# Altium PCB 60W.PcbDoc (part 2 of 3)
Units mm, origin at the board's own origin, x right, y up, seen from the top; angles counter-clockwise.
Board outline 118.9 x 83.5 mm, 3 copper layers (Top Layer, Mid-Layer 2, Bottom Layer); 99 components, 61 nets, 240 pads, 0 vias.
Unrouted connection lines stored in the file: 1.
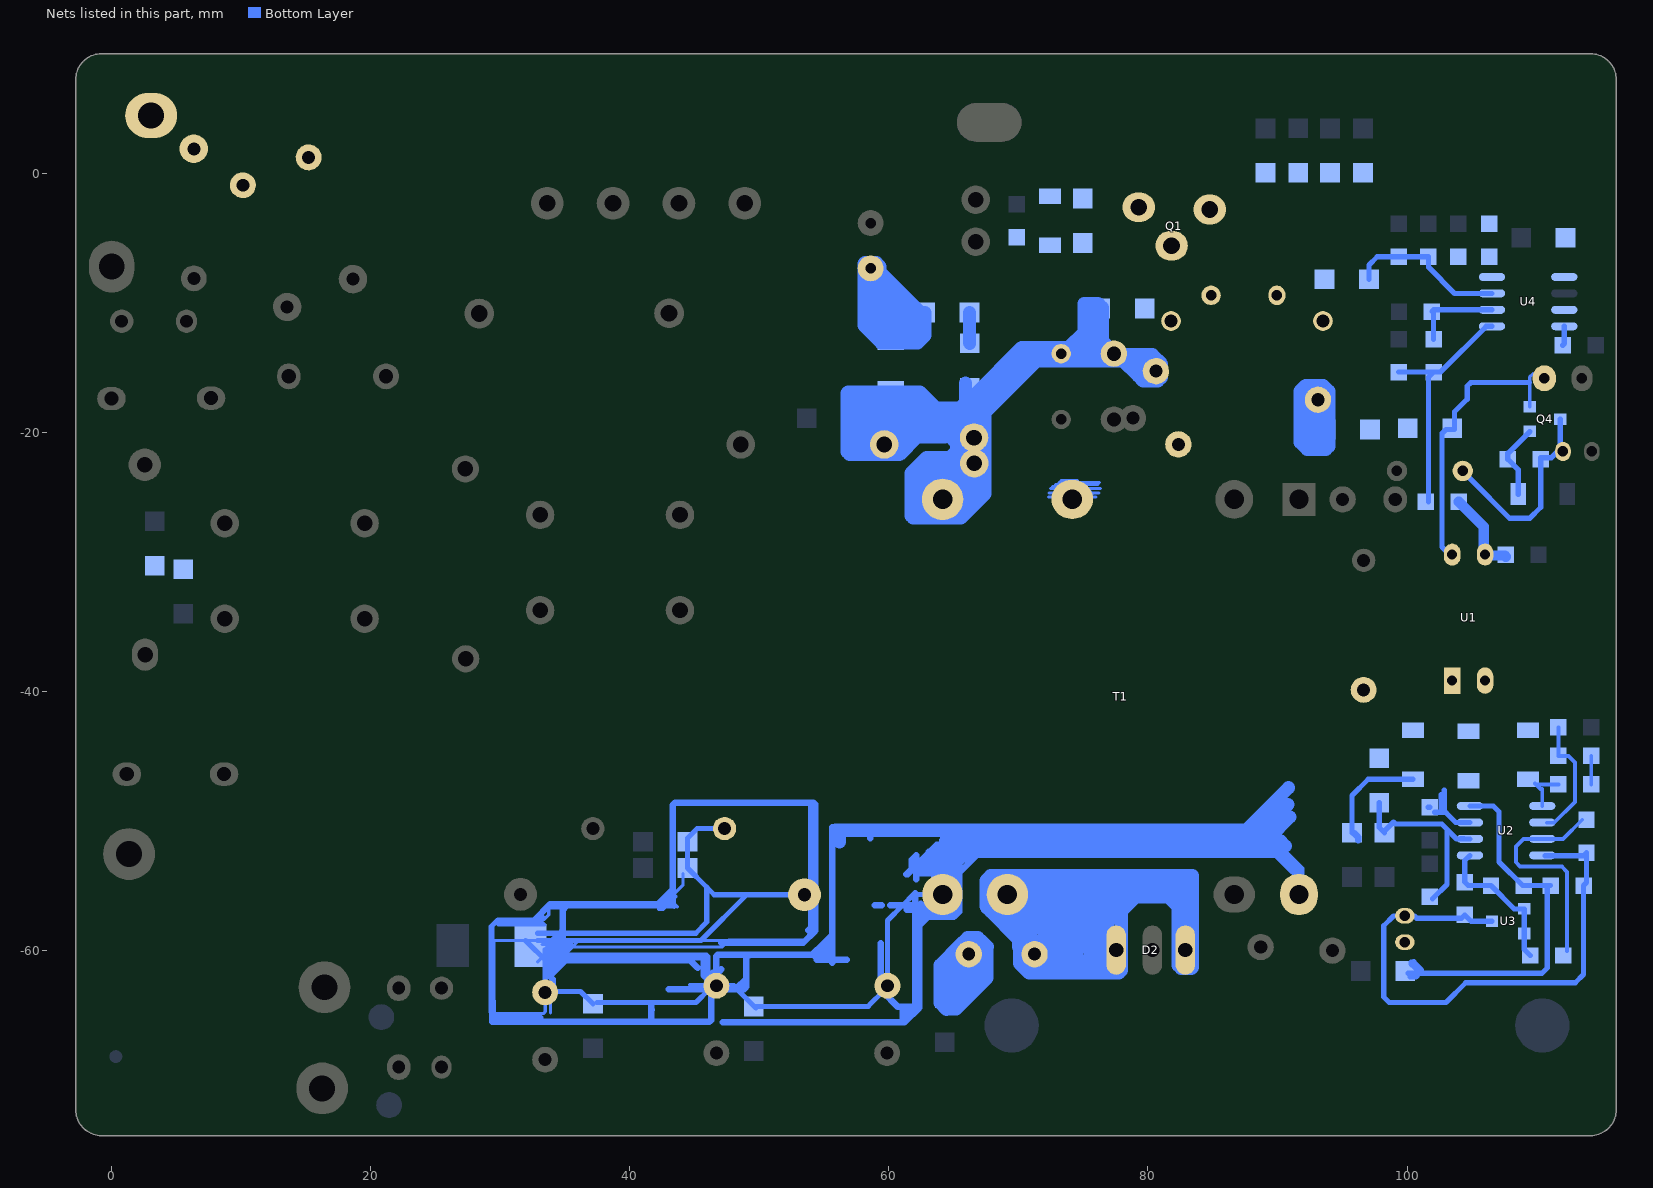
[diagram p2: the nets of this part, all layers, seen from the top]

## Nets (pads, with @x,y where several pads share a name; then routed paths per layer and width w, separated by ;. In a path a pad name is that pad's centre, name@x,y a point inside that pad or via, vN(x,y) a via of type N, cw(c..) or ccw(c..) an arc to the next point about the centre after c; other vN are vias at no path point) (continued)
NewNet1: C1.1 CB1.1 D6.1 L4.1 pad.0@66.605,-22.358 R3.1 R4.1 R11.2 R13.1 R15.2 T1.6 | length 251.5
  Bottom Layer w0.254: T1.6@64.323,-24.728 64.323,-24.509 T1.6@64.323,-23.752
  Bottom Layer w1: 57.284,-17.303 57.284,-18.878 57.284,-19.564 57.487,-19.767 57.919,-19.767 57.792,-19.64 57.792,-18.878 57.792,-16.973 57.919,-16.846 ; 57.715,-20.707 59.658,-20.707 L4.1@60.459,-20.707 ; 58.122,-18.269 58.427,-18.269 ; 58.808,-17.735 60.154,-17.735 61.144,-17.735 61.195,-17.786 ; D6.1@59.443,-17.786 60.154,-17.786 61.195,-17.786 ; 59.722,-19.107 59.417,-19.107 58.579,-18.269 58.427,-18.269 ; 61.754,-18.345 61.474,-18.065 ; 62.516,-19.056 60.51,-19.056 59.519,-18.065 60.154,-18.065 61.474,-18.065 ; T1.6@62.669,-24.771 62.669,-25.142 62.669,-25.787 63.091,-26.21 T1.6@63.177,-26.295 ; 62.719,-20.046 62.49,-20.046 62.269,-20.268 ; T1.6@62.948,-25.152 63.431,-25.635 63.431,-25.142 T1.6@63.431,-24.898 ; T1.6@63.558,-24.644 63.609,-24.592 T1.6@63.939,-24.263 ; T1.6@63.685,-24.644 63.673,-24.656 T1.6@63.431,-24.898 ; 63.812,-18.091 65.462,-18.091 ; T1.6@63.909,-25.142 64.034,-25.017 T1.6@64.182,-24.868 ; T1.6@64.182,-24.654 T1.6@64.182,-24.868 ; T1.6@64.193,-24.858 T1.6@64.182,-24.868 ; 64.193,-19.818 64.218,-19.818 ; 64.32,-20.326 62.211,-20.326 ; T1.6@64.447,-24.604 T1.6@64.432,-24.618 ; T1.6@64.548,-26.117 T1.6@64.726,-26.295 ; 64.828,-22.18 64.548,-21.901 ; 64.979,-19.996 64.396,-19.996 ; 64.98,-20.402 65.005,-20.378 ; 65.361,-20.402 65.488,-20.529 ; CB1.1@65.818,-20.351 65.818,-20.378 65.818,-22.358 65.818,-24.746 65.59,-24.974 T1.6@65.209,-24.974 ; R13.1@65.92,-16.161 65.92,-16.528 65.92,-17.634 65.462,-18.091 ; 69.501,-14.23 66.726,-17.005 65.64,-18.091 ; 75.369,-11.766 75.369,-11.919 ; 75.623,-13.697 75.572,-13.697 75.369,-13.493 75.369,-11.919 ; R15.2@75.623,-10.903 75.731,-11.011 76.029,-11.309 76.029,-12.935 76.156,-12.808 76.156,-10.42 R15.2@76.156,-10.014 ; R4.1@80.703,-15.195 80.687,-15.18 79.966,-14.459 79.077,-14.459 ; 56.776,-20.504 57.614,-21.342 59.658,-21.342 60.68,-21.342 ; 56.776,-20.504 56.776,-20.123 ; 56.776,-20.504 56.776,-21.494 56.979,-21.697 59.658,-21.697 L4.1@60.325,-21.697 ; 56.776,-20.123 56.979,-20.326 59.658,-20.326 61.696,-20.326 ; 56.776,-20.123 56.776,-18.878 56.776,-16.922 56.852,-16.846 57.919,-16.846 ; 57.919,-16.846 58.579,-16.846 ; 58.427,-18.827 58.427,-18.269 ; 58.427,-18.827 58.427,-19.691 59.004,-20.268 59.658,-20.268 61.754,-20.268 ; 58.427,-18.827 58.96,-19.361 59.658,-19.361 63.761,-19.361 ; 58.427,-18.269 58.427,-16.999 58.579,-16.846 ; 58.579,-16.846 60.154,-16.846 62.415,-16.846 64.624,-19.056 ; L4.1@60.325,-21.697 60.385,-21.637 60.68,-21.342 ; L4.1@60.325,-21.697 60.839,-21.697 62.211,-20.326 ; 60.68,-21.342 61.696,-20.326 ; 61.195,-17.786 61.474,-18.065 ; 61.195,-17.786 62.186,-17.786 63.05,-18.65 ; 61.474,-18.065 62.008,-18.065 62.592,-18.65 63.05,-18.65 ; 61.696,-20.326 62.211,-20.326 ; 61.696,-20.326 61.754,-20.268 ; 61.754,-20.268 62.269,-20.268 ; 62.211,-20.326 62.269,-20.268 ; 62.269,-20.268 64.668,-20.268 ; 62.44,-22.383 62.923,-21.901 64.548,-21.901 ; 62.44,-22.383 61.729,-23.095 61.729,-26.422 61.881,-26.574 64.159,-26.574 65.59,-26.574 65.59,-26.574 66.834,-25.33 ; 62.44,-22.383 62.44,-25.142 62.44,-25.863 62.872,-26.295 T1.6@63.177,-26.295 ; 63.05,-18.65 63.761,-19.361 ; T1.6@63.177,-26.295 64.244,-25.227 T1.6@64.432,-25.04 ; T1.6@63.177,-26.295 64.159,-26.295 T1.6@64.726,-26.295 ; T1.6@63.431,-24.898 63.431,-22.51 63.989,-21.952 63.989,-24.176 64.323,-24.509 T1.6@64.432,-24.618 ; 63.761,-19.361 64.218,-19.818 ; 64.218,-19.818 64.548,-19.818 64.967,-19.399 ; 64.218,-19.818 64.396,-19.996 ; 64.396,-19.996 64.668,-20.268 ; T1.6@64.432,-25.04 T1.6@64.432,-24.618 ; T1.6@64.432,-25.04 64.432,-25.142 64.432,-25.294 64.548,-25.177 64.548,-25.142 T1.6@64.548,-24.974 ; T1.6@64.432,-25.04 64.497,-24.974 T1.6@64.548,-24.974 ; T1.6@64.548,-24.974 T1.6@65.209,-24.974 ; T1.6@64.548,-24.974 64.548,-21.901 ; 64.548,-21.901 64.726,-21.901 ; 64.624,-19.056 65.59,-18.091 ; 64.624,-19.056 64.193,-19.488 64.193,-19.539 64.65,-19.081 ; 64.624,-19.056 64.65,-19.081 ; 64.65,-19.081 65.64,-18.091 ; 64.65,-19.081 64.967,-19.399 ; 64.668,-20.268 65.005,-20.605 ; T1.6@64.726,-26.295 65.019,-26.002 65.209,-25.812 65.209,-25.142 T1.6@65.209,-24.974 ; T1.6@64.726,-26.295 65.132,-26.295 65.222,-26.205 66.317,-25.11 66.317,-22.358 66.317,-20.378 66.317,-19.065 ; 64.726,-21.901 65.209,-21.418 ; 64.726,-21.901 65.158,-21.901 65.209,-21.85 ; 64.967,-19.399 67.044,-17.322 70.39,-13.976 71.914,-13.976 ; 64.967,-19.399 65.005,-19.436 65.005,-20.378 ; 65.005,-20.605 65.005,-20.378 ; 65.005,-20.605 65.209,-20.809 65.209,-21.418 ; 65.005,-20.378 65.792,-19.59 66.317,-19.065 ; T1.6@65.209,-24.974 65.209,-22.358 65.209,-21.85 ; 65.209,-21.85 65.209,-21.418 ; 65.462,-18.091 65.59,-18.091 ; 65.59,-18.091 66.701,-16.98 70.263,-13.417 73.311,-13.417 C1.1@73.87,-13.417 ; 65.59,-18.091 65.64,-18.091 ; 66.317,-19.065 70.924,-14.459 71.406,-14.459 ; 66.834,-25.33 66.834,-22.358 66.834,-20.378 66.834,-19.056 67.418,-18.472 ; 66.834,-25.33 67.418,-24.746 67.418,-22.358 67.418,-20.378 67.418,-18.472 ; 67.418,-18.472 71.432,-14.459 ; 67.418,-18.472 67.418,-18.447 71.406,-14.459 ; 71.406,-14.459 71.432,-14.459 ; 71.432,-14.459 73.311,-14.459 77.375,-14.459 R3.1@78.061,-14.459 ; 71.432,-14.459 71.914,-13.976 ; 71.914,-13.976 73.311,-13.976 R3.1@76.486,-13.976 ; C1.1@73.87,-13.417 75.064,-12.223 ; C1.1@73.87,-13.417 74.556,-13.417 75.064,-12.909 75.064,-12.223 ; 75.064,-12.223 75.064,-10.42 75.064,-10.014 R15.2@76.156,-10.014 ; 75.064,-12.223 75.369,-11.919 ; R15.2@76.156,-10.014 76.442,-10.299 76.486,-10.344 76.486,-10.42 76.486,-12.884 ; R3.1@76.486,-13.976 76.486,-13.9 76.486,-12.884 ; R3.1@76.486,-13.976 77.375,-13.976 R3.1@77.578,-13.976 ; 76.486,-12.884 77.439,-13.836 R3.1@77.578,-13.976 ; R3.1@77.578,-13.976 80.347,-13.976 81.058,-14.687 81.058,-15.251 81.058,-15.729 80.779,-16.008 80.616,-16.008 79.61,-16.008 79.229,-15.627 ; R3.1@78.061,-14.459 79.077,-14.459 ; R3.1@78.061,-14.459 79.229,-15.627 ; 79.077,-14.459 79.229,-14.611 79.229,-15.251 79.229,-15.627
NewNet2: 
NewNet3: R4.2 R21.2 | length 29.2
  Bottom Layer w0.6: 92.75,-20.766 92.75,-19.75 92.75,-19.475 92.85,-19.375 ; 93.35,-21.291 93.35,-19.75 93.35,-19.185 R21.2@93.377,-19.158
  Bottom Layer w1: 92.92,-20.936 92.75,-20.766 92.727,-20.743 92.361,-20.377 92.361,-19.158 ; R4.2@92.996,-17.202 R4.2@92.996,-16.948 ; 93.479,-18.904 93.479,-18.548 ; R4.2@93.479,-17.227 93.479,-17.456 R4.2@93.479,-18.218 ; 91.752,-18.752 92.158,-19.158 92.361,-19.158 ; 91.751,-18.752 91.751,-20.758 92.285,-21.291 93.35,-21.291 93.733,-21.291 93.961,-21.063 93.961,-19.75 93.961,-18.573 ; 91.752,-18.752 91.752,-18.167 ; 91.752,-18.167 92.082,-18.497 92.133,-18.548 92.361,-18.548 ; 91.752,-18.167 91.752,-17.456 91.752,-17.075 ; 91.752,-17.075 91.752,-16.77 92.094,-16.427 92.183,-16.338 93.123,-16.338 93.504,-16.338 93.872,-16.707 93.961,-16.796 93.961,-17.456 93.961,-18.167 ; 91.752,-17.075 92.628,-17.951 92.895,-18.218 93.123,-18.218 R4.2@93.479,-18.218 ; 92.361,-19.158 93.377,-19.158 93.961,-18.573 ; 92.361,-19.158 92.361,-18.548 ; 92.361,-18.548 93.123,-18.548 93.479,-18.548 ; 93.479,-18.548 93.72,-18.548 93.911,-18.548 93.961,-18.497 ; 93.479,-18.548 R4.2@93.479,-18.218 ; R4.2@93.479,-18.218 93.911,-18.218 93.961,-18.167 ; 93.961,-18.573 93.961,-18.497 ; 93.961,-18.497 93.961,-18.167
NewNet4: R6.1 R7.2
NewNet5: C4.1 R2.2 | length 29.9
  Bottom Layer w1: 64.447,-64.497 65.183,-64.497 65.189,-64.49 67.596,-62.084 67.596,-60.25 67.596,-59.671 ; R2.2@66.885,-60.509 67.012,-60.636 67.012,-62.262
  Bottom Layer w1.016: 64.447,-64.497 63.964,-64.014 63.964,-63.621 63.964,-62.668 ; C4.1@64.523,-63.1 65.564,-62.058 ; 65.005,-60.229 63.964,-61.271 ; C4.1@65.031,-63.15 64.65,-63.531 65.234,-63.531 ; 65.564,-62.871 65.996,-62.439 65.996,-62.414 65.602,-62.02 ; 66.352,-62.045 66.352,-61.271 ; R2.2@66.352,-59.696 66.352,-60.25 R2.2@66.352,-60.28 ; R2.2@66.936,-60.28 66.631,-59.975 66.631,-60.001 R2.2@66.352,-60.28 ; 67.596,-59.671 67.175,-59.249 66.885,-58.959 66.174,-58.959 66.098,-58.959 65.491,-59.566 63.964,-61.093 63.964,-61.271 ; 63.964,-62.668 63.964,-61.271 ; 63.964,-62.668 66.278,-60.354 R2.2@66.352,-60.28 ; 65.564,-62.058 65.602,-62.02 ; 65.564,-62.058 65.564,-61.982 65.602,-62.02 ; 65.602,-62.02 66.352,-61.271 ; 66.352,-61.271 R2.2@66.352,-60.28
NewNet6: R12.1 R13.2 | length 2.4
  Bottom Layer w1: R12.1@66.237,-10.725 66.237,-13.087 R13.2@66.25,-13.1
NewNet7: D6.2 E4.1 R12.2 | length 40.3
  Bottom Layer w1: E4.1@58.63,-7.42 58.63,-11.995 59.227,-12.592 D6.2@60.154,-12.592 ; 59.239,-8.414 59.239,-11.538 59.798,-12.097 60.154,-12.097 62.364,-12.097 62.516,-11.944 R12.2@62.516,-11.258 ; 59.925,-8.871 59.925,-10.928 60.382,-11.385 62.008,-11.385 ; 60.23,-10.319 60.687,-10.776 61.348,-10.776 ; 60.382,-9.43 60.382,-9.811 61.348,-10.776 ; 61.906,-10.776 61.348,-10.776 ; 58.096,-11.741 59.417,-13.062 60.154,-13.062 62.237,-13.062 62.809,-12.49 R12.2@62.809,-10.725 62.465,-10.725 59.341,-7.601 59.341,-7.319 59.341,-7.169 59.048,-6.876 59.036,-6.864 58.604,-6.864 58.173,-6.864 58.161,-6.876 58.096,-6.94 58.096,-7.319 58.096,-11.741
NewNet8: D2.1 D2.3 R2.1 T1.8 | length 206.1
  Bottom Layer w0.3: 70.949,-59.125 71.254,-59.125 72.562,-59.125 73.223,-59.125 73.825,-59.125 ; 70.949,-58.9 72.337,-58.9 72.6,-58.9
  Bottom Layer w1.016: T1.8@68.511,-54.997 T1.8@68.882,-54.997 ; T1.8@68.909,-55.642 T1.8@69.159,-55.642 71.381,-55.642 ; T1.8@69.019,-55.403 69.159,-55.403 72.422,-55.403 ; T1.8@69.12,-55.911 69.159,-55.911 71.111,-55.911 ; 70.543,-61.195 71.051,-61.703 71.254,-61.703 74.454,-61.703 ; 70.822,-61.703 70.312,-61.192 70.085,-60.966 70.085,-60.25 70.085,-59.747 ; R2.1@71.432,-59.696 73.133,-59.696 ; D2.3@76.969,-59.95 76.715,-59.696 ; D2.3@77.578,-61.296 D2.3@77.375,-61.093 ; 82.608,-55.124 82.862,-54.87 82.862,-55.657 ; 82.862,-57.08 82.862,-55.657 ; D2.1@83.09,-58.172 82.557,-57.639 82.557,-56.826 82.328,-56.597 ; T1.8@68.882,-54.997 69.095,-55.21 69.159,-55.21 72.229,-55.21 72.422,-55.403 ; T1.8@68.882,-54.997 69.159,-54.997 73.667,-54.997 77.756,-59.086 77.705,-59.086 74.022,-55.403 72.422,-55.403 ; T1.8@69.044,-56.038 70.39,-57.385 70.39,-57.054 70.289,-56.953 70.39,-56.953 72.337,-58.9 72.562,-59.125 73.133,-59.696 ; T1.8@69.044,-56.038 68.903,-55.898 68.638,-55.632 68.638,-55.642 68.638,-56.521 69.933,-57.816 69.933,-59.01 ; T1.8@69.044,-56.038 68.765,-56.038 70.949,-58.223 70.949,-58.9 70.949,-59.125 70.949,-59.772 71.254,-60.077 R2.1@71.254,-60.25 R2.1@71.254,-60.61 ; T1.8@69.044,-56.038 69.159,-56.038 71.061,-56.038 ; 69.933,-59.01 70.035,-59.112 ; 69.933,-59.01 67.862,-56.939 67.495,-56.572 67.495,-55.642 67.495,-54.565 67.788,-54.271 67.876,-54.184 69.159,-54.184 73.591,-54.184 ; 70.035,-59.112 70.035,-59.696 70.085,-59.747 ; 70.035,-59.112 70.085,-59.163 70.085,-59.747 ; 70.085,-59.747 70.921,-60.583 R2.1@70.949,-60.61 ; R2.1@70.949,-60.61 R2.1@71.254,-60.915 ; R2.1@70.949,-60.61 R2.1@71.254,-60.61 ; 71.061,-56.038 71.061,-56.963 73.223,-59.125 73.794,-59.696 ; 71.061,-56.038 71.061,-55.962 71.111,-55.911 ; 71.061,-56.038 71.533,-56.038 ; 71.111,-55.911 71.406,-55.911 71.533,-56.038 ; 71.111,-55.911 71.381,-55.642 ; R2.1@71.254,-60.915 R2.1@71.254,-60.61 ; R2.1@71.254,-60.915 73.667,-60.915 ; R2.1@71.254,-60.61 73.362,-60.61 73.667,-60.915 ; 71.381,-55.642 71.924,-55.642 ; 71.533,-56.038 75.191,-59.696 ; 71.533,-56.038 72.321,-56.038 ; 71.924,-55.642 72.321,-56.038 ; 71.924,-55.642 72.661,-55.642 ; 72.321,-56.038 75.978,-59.696 ; 72.422,-55.403 72.661,-55.642 ; 72.661,-55.642 76.715,-59.696 ; 72.661,-55.642 73.474,-55.642 77.528,-59.696 76.715,-59.696 ; 73.133,-59.696 73.794,-59.696 ; 73.133,-59.696 75.14,-61.703 ; 73.591,-54.184 76.131,-54.184 ; 73.591,-54.184 76.943,-57.537 76.943,-57.766 77.223,-57.486 77.223,-55.276 76.131,-54.184 ; 73.667,-60.915 74.454,-61.703 ; 73.794,-59.696 75.191,-59.696 ; 73.794,-59.696 75.572,-61.474 75.572,-60.585 76.08,-61.093 D2.3@77.375,-61.093 ; 74.454,-61.703 75.14,-61.703 ; 75.14,-61.703 77.553,-61.703 77.756,-61.703 77.959,-61.499 77.959,-59.933 77.959,-56.927 ; 75.191,-59.696 75.978,-59.696 ; 75.191,-59.696 75.496,-60.001 76.283,-60.001 ; 75.978,-59.696 76.715,-59.696 ; 75.978,-59.696 76.283,-60.001 ; 76.131,-56.064 76.435,-56.369 76.435,-55.505 76.131,-55.2 ; 76.131,-56.064 75.877,-56.064 74.302,-54.489 75.419,-54.489 76.131,-55.2 ; 76.131,-56.064 76.131,-55.2 ; 76.131,-55.2 76.131,-54.184 ; 76.131,-54.184 76.842,-54.184 ; 76.283,-60.001 76.884,-60.602 D2.3@77.375,-61.093 ; 76.842,-54.184 83.446,-54.184 83.446,-59.933 D2.1@83.446,-60.687 ; 76.842,-54.184 77.959,-55.302 77.959,-56.191 ; 77.959,-56.927 77.959,-56.191 ; 77.959,-56.927 79.052,-55.835 ; 77.959,-56.191 78.417,-55.734 ; 78.417,-55.734 78.518,-55.835 79.052,-55.835 ; 78.417,-55.734 78.137,-55.454 78.696,-55.454 ; 78.417,-55.734 78.696,-55.454 ; 78.696,-55.454 81.185,-55.454 81.566,-55.835 ; 78.696,-55.454 78.086,-54.845 82.049,-54.845 82.862,-55.657 ; 79.052,-55.835 81.566,-55.835 ; 81.566,-55.835 82.176,-55.835 82.328,-55.988 82.328,-56.597 ; 81.566,-55.835 82.328,-56.597 ; D2.1@82.328,-60.382 82.328,-61.118 82.557,-61.347 82.887,-61.347 83.37,-61.347 83.446,-61.271 D2.1@83.446,-60.687 ; D2.1@82.328,-60.382 82.328,-59.933 82.328,-56.597 ; D2.1@82.328,-60.382 82.383,-60.437 82.836,-60.89 82.887,-60.89 83.243,-60.89 D2.1@83.446,-60.687
PE: CY1.2 CY2.1 CY3.1 pad.2@3.072,4.475
Q3_1: D7.1 Q1.1 R14.2 R16.1
Q3_2: C2.2 Q1.2 R17.2 R19.2 R23.2 R27.2 R36.1
Q3_3: C2.1 D3.1 Q1.3 T1.4 | length 25.6
  Bottom Layer w0.254: 72.337,-24.966 74.085,-24.966 74.159,-24.966 75.972,-24.966 ; 72.38,-24.65 74.159,-24.65 74.401,-24.65 74.486,-24.65 T1.4@75.645,-24.65 ; 72.498,-24.3 74.159,-24.3 T1.4@75.295,-24.3 ; 72.657,-24.15 74.159,-24.15 T1.4@75.145,-24.15 ; 72.872,-24.002 74.159,-24.002 T1.4@74.997,-24.002 ; 73.156,-23.85 74.159,-23.85 76.251,-23.85 ; 73.322,-23.719 74.159,-23.719 T1.4@74.573,-23.719 ; T1.4@75.204,-24.15 T1.4@75.145,-24.15 ; 75.722,-24.727 T1.4@75.645,-24.65 ; 76.12,-24.002 T1.4@74.997,-24.002 ; 76.207,-24.65 T1.4@75.645,-24.65 ; 76.341,-24.3 T1.4@75.295,-24.3 ; T1.4@74.997,-24.002 T1.4@75.145,-24.15 ; T1.4@75.145,-24.15 75.148,-24.153 T1.4@75.295,-24.3 ; T1.4@75.295,-24.3 T1.4@75.645,-24.65
  Bottom Layer w1: T1.4@73.464,-25.279 74.159,-25.279 74.226,-25.279 74.261,-25.244 T1.4@74.363,-25.142 ; T1.4@73.718,-24.39 T1.4@73.921,-24.39 ; T1.4@74.611,-24.776 74.568,-24.733 74.486,-24.65 74.48,-24.644 74.407,-24.644 74.401,-24.65 74.085,-24.966 74.034,-25.017 73.845,-25.206 74.153,-25.206 74.188,-25.171 74.217,-25.142 T1.4@74.363,-25.142 ; T1.4@74.734,-25.142 T1.4@74.363,-25.142
Q4_B: DZ1.2 Q4.3 R35.2 | length 5.9
  Bottom Layer w0.406: DZ1.2@108.575,-24.75 108.575,-22.845 R35.2@107.78,-22.05 107.78,-21.595 Q4.3@109.475,-19.9
Q4_C: E7.1 Q4.1 R5.1 R35.1 | length 15.4
  Bottom Layer w0.406: R5.1@104.302,-22.982 104.748,-23.427 104.945,-23.625 107.93,-26.61 109.46,-26.61 110.32,-25.75 R35.1@110.32,-22.05 ; R35.1@110.32,-21.925 111.142,-21.925 E7.1@111.617,-21.45 ; E7.1@111.825,-21.241 Q4.1@111.825,-18.95
R3_2: pad.0@81.79,-11.38 pad.1@93.51,-11.38 R15.1 R22.2
R15_1: 
R22_1: R18.1 ZD1.2 | length 8.7
  Bottom Layer w0.4: R18.1@95.75,-50.87 95.75,-48 97,-46.75 ZD1.2@100.45,-46.75
  Bottom Layer w0.508: R18.1@95.943,-50.933 96.222,-51.212 R18.1@96.222,-51.466
R24_2: C11.1 R39.2 | length 2.2
  Bottom Layer w0.3: C11.1@114.22,-47.15 R39.2@114.22,-44.95
R35_2: R21.1 R29.2
R36_2: 
R47_2: 
U1_1: R26.1 R31.1 R32.2 U4.1 | length 18.8
  Bottom Layer w0.406: R26.1@99.35,-15.32 R32.2@102.05,-15.32 ; R31.1@101.65,-25.325 101.65,-16.32 101.65,-15.72 R32.2@102.05,-15.32 ; U4.1@106.55,-11.79 106.12,-11.79 102.59,-15.32 R32.2@102.05,-15.32
U1_2: C6.1 R32.1 U4.2 | length 6.9
  Bottom Layer w0.406: C6.1@101.92,-10.65 C6.1@102.05,-10.52 ; R32.1@102.05,-12.78 102.05,-10.65 C6.1@102.05,-10.52 ; U4.2@106.55,-10.52 C6.1@102.05,-10.52
U1_3: C7.2 R22.1 R30.2 U4.3 | length 12.5
  Bottom Layer w0.406: R22.1@97.065,-8.15 97.065,-7.06 97.705,-6.42 R30.2@99.35,-6.42 C7.2@101.65,-6.42 101.65,-7.225 103.675,-9.25 U4.3@106.55,-9.25
U1_4: C9.1 R36.2 U4.4
U1_5: R38.1 U4.5
U1_7: D7.2 R16.2 U4.7
U1_8: C12.2 E6.1 Q4.2 R29.1 U1.4 U4.8 | length 23.7
  Bottom Layer w0.254: Q4.2@109.475,-18 109.475,-15.7 109.725,-15.45
  Bottom Layer w0.406: U1.4@103.38,-29.49 102.7,-28.81 102.7,-20.05 103,-19.75 103.479,-19.75 103.664,-19.75 103.664,-19.65 103.664,-18.386 104.63,-17.42 104.65,-17.42 104.65,-16.4 104.925,-16.125 109.45,-16.125 ; C12.2@112.01,-13.25 112.138,-13.122 U4.8@112.138,-11.79
U2_1: C11.2 D9.2 U2.1 | length 3.6
  Bottom Layer w0.3: D9.2@109.875,-47.075 110.288,-47.488 110.438,-47.488 U2.1@110.438,-48.81 ; D9.2@110.1,-47.15 C11.2@111.68,-47.15
U2_2: R39.1 R40.1 U2.2 | length 9.5
  Bottom Layer w0.3: U2.2@110.8,-50.1 111.35,-50.1 112.95,-48.5 112.95,-45.45 112.45,-44.95 R39.1@111.68,-44.95 R40.1@111.68,-42.75
U2_3: R37.1 R41.2 U2.3 | length 17.6
  Bottom Layer w0.3: R37.1@112.35,-60 112.35,-53.9 111.95,-53.5 111.95,-53.475 108.725,-53.475 108.4,-53.15 108.4,-51.925 108.975,-51.35 U2.3@110.438,-51.35 112.05,-51.35 R41.2@113.525,-49.875
U2_4: 
U2_5: C8.2 R33.2 R37.2 U2.5 U3.1 U3.2 | length 11.5
  Bottom Layer w0.4: U2.5@104.85,-52.62 104.45,-53.02 C8.2@104.45,-54.68 104.72,-54.95 R33.2@106.48,-54.95 108.28,-56.75 U3.1@109.05,-56.75 U3.2@109.05,-58.65 109.05,-59.89 R37.2@109.51,-60.35
U2_6: R20.1 R25.2 R28.2 U2.6 | length 15.9
  Bottom Layer w0.4: R25.2@97.85,-48.564 97.85,-50.469 R20.1@98.25,-50.87 ; R20.1@98.325,-50.675 98.95,-50.05 99.01,-50.11 99.1,-50.2 102.675,-50.2 103.073,-50.598 ; R28.2@101.975,-55.975 103.073,-54.877 103.073,-50.598 ; U2.6@104.125,-51.325 U2.6@104.4,-51.325 ; U2.6@104.85,-51.35 103.825,-51.35 103.073,-50.598
U2_7: C5.2 D8.2 U2.7 | length 6.4
  Bottom Layer w0.4: C5.2@101.608,-48.903 C5.2@101.75,-48.903 ; C5.2@102.109,-49.291 102.975,-49.291 103.764,-50.08 U2.7@104.85,-50.08 ; 102.639,-49.254 102.639,-47.946 ; 102.871,-47.58 102.871,-49.187 103.035,-49.351
U2_8: C10.1 E5.1 R24.1 R33.1 U2.8 | length 31.3
  Bottom Layer w0.4: R24.1@100.072,-61.725 100.975,-61.725 ; R24.1@100.222,-62 100.7,-62 100.975,-61.725 ; R24.1@100.3,-60.85 100.3,-61 100.357,-61.058 101.025,-61.725 ; R24.1@100.522,-60.8 100.522,-60.872 100.532,-60.882 101.125,-61.475 ; U2.8@104.85,-48.81 106.66,-48.81 107.1,-49.25 107.1,-53.125 108.925,-54.95 R33.1@109.02,-54.95 C10.1@110.75,-54.95 ; C10.1@111.08,-54.95 C10.1@110.75,-54.95 ; 100.975,-61.725 101.025,-61.725 ; 101.025,-61.725 110.425,-61.725 110.825,-61.325 110.825,-55.025 C10.1@110.75,-54.95
U3_3: C3.2 C8.1 C10.2 CY4.2 D1.2 E1.0 E2.0 E3.0 E5.2 R1.2 R8.1 R9.2 R10.2 R25.1 R41.1 RS1.1 T1.7 T1.12 U2.4 U3.3 | length 740.1
  Bottom Layer w0.254: 29.44,-59.188 29.44,-58.106 29.806,-57.74 32.671,-57.74 ; 29.522,-64.674 29.522,-59.366 ; 29.837,-57.969 32.349,-57.969 RS1.1@32.443,-57.969 ; RS1.1@32.9,-60.839 33.252,-60.486 33.263,-60.476 RS1.1@33.408,-60.331 ; RS1.1@33.255,-59.493 33.789,-59.493 34.17,-59.493 34.246,-59.493 ; RS1.1@33.586,-60.052 RS1.1@33.586,-59.874 ; 33.89,-64.776 33.89,-63.192 33.89,-63.125 E1.0@33.89,-62.719 ; 34.83,-58.959 35.059,-59.188 ; 43.669,-56.597 43.441,-56.369 ; R9.2@44.127,-54.032 44.127,-54.895 42.755,-56.267 ; 44.635,-62.617 45.727,-62.617 45.981,-62.363 E2.0@45.981,-62.312 ; 65.59,-52.711 65.971,-52.711 66.682,-52.711 88.986,-52.711 ; 29.242,-59.467 29.242,-64.751 29.318,-64.827 ; 29.242,-59.467 29.242,-58.096 29.801,-57.537 32.544,-57.537 33.814,-56.267 42.349,-56.267 42.755,-56.267 ; 29.242,-59.467 29.522,-59.188 ; 29.318,-64.827 29.42,-64.827 33.332,-64.827 33.484,-64.674 E1.0@33.484,-63.192 33.484,-62.744 33.408,-62.668 33.408,-61.855 ; 29.318,-64.827 29.42,-64.725 29.42,-59.467 29.522,-59.366 ; 29.522,-59.366 29.522,-59.188 ; 29.522,-59.188 31.975,-59.188 32.349,-59.188 34.094,-59.188 34.475,-59.188 34.551,-59.188 ; RS1.1@32.443,-57.969 33.459,-57.969 33.23,-57.74 32.671,-57.74 ; RS1.1@32.443,-57.969 32.671,-57.74 ; 32.671,-57.74 32.867,-57.545 ; 32.867,-57.545 33.426,-57.545 33.763,-57.207 33.763,-56.648 ; 32.867,-57.545 33.099,-57.312 ; 33.099,-57.312 33.202,-57.209 ; 33.099,-57.312 33.22,-57.433 33.426,-57.433 33.202,-57.209 ; 33.202,-57.209 33.763,-56.648 ; 33.408,-61.855 33.408,-61.626 ; 33.408,-61.855 33.484,-61.779 34.673,-60.59 ; 33.408,-61.626 33.408,-61.398 ; 33.408,-61.626 33.484,-61.55 35.214,-59.82 ; 33.408,-61.398 33.408,-61.296 ; 33.408,-61.398 33.484,-61.322 33.514,-61.291 RS1.1@33.514,-61.19 ; 33.408,-61.296 RS1.1@33.408,-60.763 ; 33.408,-61.296 33.484,-61.22 RS1.1@33.514,-61.19 ; RS1.1@33.408,-60.763 RS1.1@33.408,-60.636 ; RS1.1@33.408,-60.763 33.468,-60.702 33.479,-60.692 33.484,-60.687 33.687,-60.687 34.553,-59.82 ; RS1.1@33.408,-60.636 33.408,-60.621 RS1.1@33.408,-60.331 ; RS1.1@33.408,-60.636 33.415,-60.628 34.223,-59.82 ; RS1.1@33.408,-60.331 RS1.1@33.408,-59.874 ; RS1.1@33.408,-60.331 33.865,-59.874 ; RS1.1@33.408,-59.874 RS1.1@33.586,-59.696 ; RS1.1@33.408,-59.874 RS1.1@33.586,-59.874 ; RS1.1@33.514,-61.19 33.735,-60.969 34.884,-59.82 ; RS1.1@33.514,-61.19 33.514,-60.91 33.595,-60.829 34.604,-59.82 ; RS1.1@33.586,-59.874 RS1.1@33.586,-59.696 ; RS1.1@33.586,-59.874 33.865,-59.874 ; RS1.1@33.586,-59.696 34.043,-59.696 ; 33.763,-56.648 33.967,-56.445 35.16,-56.445 34.932,-56.673 33.789,-56.673 33.763,-56.648 ; 33.865,-59.874 33.918,-59.82 ; 33.918,-59.82 34.043,-59.696 ; 33.918,-59.82 34.223,-59.82 ; 34.043,-59.696 34.246,-59.493 ; 34.043,-59.696 34.348,-59.696 ; 34.223,-59.82 34.348,-59.696 ; 34.223,-59.82 34.553,-59.82 ; 34.246,-59.493 34.551,-59.188 ; 34.246,-59.493 35.541,-59.493 35.656,-59.607 ; 34.348,-59.696 35.414,-59.696 ; 34.551,-59.188 34.83,-59.188 35.059,-59.188 ; 34.553,-59.82 34.604,-59.82 ; 34.604,-59.82 34.884,-59.82 ; 34.673,-60.59 35.567,-59.696 ; 34.673,-60.59 35.181,-60.59 45.605,-60.59 ; 34.884,-59.82 35.214,-59.82 ; 35.059,-59.188 35.262,-59.188 ; 35.214,-59.82 35.29,-59.82 35.414,-59.696 ; 35.262,-59.188 35.668,-59.594 ; 35.262,-59.188 36.075,-59.188 ; 35.414,-59.696 35.567,-59.696 ; 35.567,-59.696 35.656,-59.607 ; 35.567,-59.696 35.745,-59.696 ; 35.656,-59.607 35.668,-59.594 ; 35.656,-59.607 35.745,-59.696 ; 35.668,-59.594 36.075,-59.188 ; 35.668,-59.594 35.77,-59.696 ; 35.745,-59.696 35.77,-59.696 ; 35.77,-59.696 47.124,-59.696 47.454,-59.366 47.632,-59.188 ; 36.075,-59.188 45.512,-59.188 47.632,-59.188 ; 42.755,-56.267 42.247,-56.775 42.603,-56.775 42.796,-56.582 ; 42.796,-56.582 43.4,-56.582 43.441,-56.623 43.441,-56.369 ; 42.796,-56.582 43.009,-56.369 ; 43.009,-56.369 43.441,-56.369 ; 43.009,-56.369 43.441,-55.937 ; 43.441,-56.369 43.441,-55.937 ; 43.441,-55.937 43.441,-55.886 43.568,-55.759 43.568,-55.81 43.441,-55.937 ; 45.605,-60.59 45.605,-61.936 E2.0@45.981,-62.312 ; 45.605,-60.59 45.981,-60.966 E2.0@45.981,-62.312 ; 47.632,-59.188 53.296,-59.188 53.321,-59.163 47.657,-59.163 47.632,-59.188
  Bottom Layer w0.4: RS1.1@31.975,-59.188 32.359,-59.573 33.263,-60.476 33.408,-60.621 33.415,-60.628 33.479,-60.692 33.484,-60.697 33.484,-61.22 33.484,-61.322 33.484,-61.55 33.484,-61.779 33.484,-62.744 E1.0@33.484,-63.192 ; RS1.1@32.9,-59.188 34.094,-59.188 34.475,-59.188 34.551,-59.188 34.83,-59.188 35.059,-59.188 35.262,-59.188 36.075,-59.188 45.512,-59.188 49.043,-55.657 ; RS1.1@32.9,-58.625 34.657,-58.625 34.83,-58.625 45.1,-58.625 45.95,-57.775 45.95,-55.08 ; E1.0@33.89,-63.125 36.215,-63.125 R8.1@37.167,-64.077 ; R8.1@37.475,-63.975 45.125,-63.975 46.153,-62.947 46.286,-62.814 E2.0@46.5,-62.6 ; E2.0@46.692,-62.684 48.034,-62.684 48.257,-62.907 48.297,-62.947 49.609,-64.26 C3.2@49.631,-64.281 ; D1.2@47.327,-50.552 45.223,-50.552 44.47,-51.305 R10.2@44.47,-51.568 R9.2@44.47,-53.6 45.95,-55.08 ; C3.2@49.588,-64.281 C3.2@49.631,-64.281 ; C3.2@49.75,-64.4 C3.2@49.631,-64.281 ; R1.2@53.499,-55.657 49.043,-55.657 ; 58.444,-64.281 C3.2@49.631,-64.281 ; 58.575,-64.1 59.534,-63.141 59.7,-62.975 E3.0@59.7,-62.95 ; E3.0@59.9,-62.684 59.9,-57.65 61.08,-56.47 61.908,-55.642 62.034,-55.642 63.909,-55.642 63.909,-54.438 63.909,-54.061 63.909,-53.824 63.909,-53.782 63.909,-53.473 63.909,-53.325 63.909,-53.092 63.909,-53.02 63.909,-52.817 64.193,-52.533 64.396,-52.33 64.497,-52.228 64.574,-52.152 64.904,-51.822 65.101,-51.625 65.266,-51.625 87.1,-51.625 89.872,-51.625 91.875,-53.628 91.875,-55.642 T1.12@91.875,-55.8 ; U3.3@106.55,-57.7 104.93,-57.7 C8.1@104.45,-57.22 104.195,-57.475 100.75,-57.475 100.564,-57.289 E5.2@99.834,-57.289 98.961,-57.289 98.2,-58.05 98.2,-63.55 98.625,-63.975 103,-63.975 104.525,-62.45 112.975,-62.45 113.62,-61.805 C10.2@113.62,-54.95 113.85,-54.72 R41.1@113.85,-52.42 113.62,-52.65 U2.4@110.65,-52.65 ; 45.95,-55.08 46.527,-55.657 49.043,-55.657
  Bottom Layer w0.5: 61.38,-56.802 62.034,-56.802 62.338,-56.802 62.797,-56.802 64.159,-56.802 65.359,-56.802 65.422,-56.802 ; 61.709,-56.47 62.034,-56.47 62.211,-56.47 62.465,-56.47 64.159,-56.47 T1.7@65.351,-56.47
  Bottom Layer w0.508: 29.395,-65.462 29.471,-65.462 ; 29.42,-63.887 29.42,-64.725 29.42,-64.827 29.42,-65.157 ; 33.103,-65.157 29.42,-65.157 ; 33.789,-59.493 34.094,-59.188 34.657,-58.625 34.83,-58.451 ; E1.0@34.068,-62.592 34.068,-62.185 33.763,-61.88 33.89,-61.88 35.049,-60.722 ; 34.17,-59.493 34.475,-59.188 34.83,-58.832 ; 34.83,-59.188 34.83,-58.959 34.83,-58.832 ; 41.663,-64.268 41.663,-64.573 ; 41.688,-64.547 41.663,-64.573 ; 43.034,-62.947 46.153,-62.947 E2.0@46.286,-62.947 ; 45.244,-61.296 44.67,-60.722 35.049,-60.722 ; E2.0@45.981,-62.312 45.981,-60.966 45.981,-60.458 45.905,-60.382 35.389,-60.382 35.181,-60.59 35.049,-60.722 ; E2.0@46.26,-62.236 E2.0@46.286,-62.211 ; 46.438,-61.677 46.286,-61.83 E2.0@46.286,-62.211 ; E2.0@46.692,-62.236 E2.0@46.692,-61.804 ; 47.073,-61.423 E2.0@46.692,-61.804 ; 47.073,-59.366 47.454,-59.366 53.398,-59.366 54.312,-58.451 54.312,-55.657 54.312,-48.698 54.16,-48.545 54.033,-48.545 ; 47.175,-65.513 61.195,-65.513 61.627,-65.081 ; 49.207,-60.306 54.083,-60.306 55.023,-59.366 ; 49.715,-60.306 49.206,-60.306 ; 53.804,-58.401 54.033,-58.172 54.033,-55.657 54.033,-48.545 ; 54.363,-60.483 54.388,-60.483 55.023,-59.848 ; 54.947,-60.149 54.947,-60.179 ; 55.557,-58.883 55.074,-59.366 55.023,-59.366 ; 55.633,-60.89 55.633,-60.687 ; 56.75,-60.687 55.633,-60.687 ; 58.579,-51.289 58.579,-50.89 58.368,-50.679 58.165,-50.476 55.633,-50.476 ; 58.935,-56.47 59.468,-56.47 ; 58.96,-50.45 55.658,-50.45 55.633,-50.476 ; 59.367,-59.417 59.367,-62.684 59.367,-62.973 59.489,-63.095 59.534,-63.141 60.713,-64.319 61.272,-64.319 ; 60.129,-56.47 61.08,-56.47 62.034,-56.47 ; 61.272,-65.462 62.338,-64.395 62.338,-58.045 ; 61.78,-64.319 61.272,-64.319 ; 62.034,-55.556 62.034,-55.642 62.034,-56.47 ; 62.135,-54.464 62.135,-53.752 ; 62.465,-56.369 62.465,-56.47 ; 62.618,-56.978 62.618,-57.207 62.465,-57.359 63.024,-57.359 ; 63.05,-53.371 63.05,-53.244 ; 63.1,-52.33 63.202,-52.33 ; 63.583,-52.559 63.431,-52.711 ; 63.685,-53.981 63.685,-53.6 ; T1.7@63.786,-54.438 63.909,-54.438 64.159,-54.438 64.421,-54.438 T1.7@64.497,-54.438 ; T1.7@65.209,-55.734 T1.7@65.437,-55.962 ; 65.437,-52.482 65.437,-52.838 ; 67.063,-52.33 66.682,-52.711 65.437,-53.956 ; 29.42,-65.157 29.42,-65.411 29.471,-65.462 ; 29.471,-65.462 41.841,-65.462 ; 34.83,-58.832 34.83,-58.625 34.83,-58.451 ; 34.83,-58.451 34.83,-56.826 35.186,-56.47 42.145,-56.47 42.349,-56.267 43.314,-55.302 43.314,-48.749 43.517,-48.545 54.033,-48.545 ; 41.663,-64.573 41.663,-65.284 41.841,-65.462 ; 41.841,-65.462 46.159,-65.462 46.286,-65.335 E2.0@46.286,-62.947 ; E2.0@46.286,-62.947 46.692,-62.947 48.216,-62.947 ; E2.0@46.286,-62.947 46.286,-62.814 46.286,-62.684 E2.0@46.286,-62.211 ; E2.0@46.286,-62.211 E2.0@46.692,-61.804 ; E2.0@46.692,-61.804 46.692,-60.407 46.793,-60.306 49.206,-60.306 ; 48.216,-62.947 48.297,-62.947 48.826,-62.947 49.003,-62.769 49.003,-62.16 ; 48.216,-62.947 48.257,-62.907 49.003,-62.16 ; 49.003,-62.16 49.003,-60.509 49.206,-60.306 ; 54.947,-60.179 54.439,-60.687 55.633,-60.687 ; 54.947,-60.179 55.023,-60.102 55.023,-59.848 ; 54.947,-60.179 54.947,-60.661 55.379,-60.229 55.379,-59.493 55.023,-59.848 ; 55.023,-59.848 55.023,-59.366 ; 55.023,-59.366 55.633,-58.756 ; 55.633,-60.687 55.633,-58.756 ; 55.633,-58.756 55.633,-50.476 ; 61.272,-64.319 61.094,-64.497 61.094,-65.208 62.034,-64.268 62.034,-56.802 62.034,-56.47 ; 61.957,-53.575 62.135,-53.752 ; 61.957,-53.575 62.135,-53.575 ; 61.957,-53.575 61.449,-54.083 61.348,-54.083 61.78,-53.651 61.78,-52.965 62.135,-52.609 62.135,-53.397 ; 61.957,-53.575 62.135,-53.397 ; 62.034,-56.47 62.211,-56.47 ; 62.135,-53.752 62.135,-53.575 ; 62.135,-53.752 62.364,-53.981 63.278,-53.981 63.456,-53.803 63.456,-53.575 ; 62.135,-53.575 62.135,-53.397 ; 62.135,-53.575 63.456,-53.575 ; 62.135,-53.397 63.202,-52.33 ; 62.211,-56.47 62.338,-56.597 62.338,-56.802 62.338,-58.045 ; 62.211,-56.47 62.465,-56.47 ; 62.338,-58.045 63.024,-57.359 ; 62.465,-56.47 62.797,-56.802 62.898,-56.903 63.151,-57.156 64.159,-57.156 65.005,-57.156 65.339,-56.822 65.359,-56.802 65.437,-56.724 ; 62.465,-56.47 64.159,-56.47 T1.7@65.437,-56.47 ; 63.024,-57.359 64.159,-57.359 65.031,-57.359 65.437,-56.953 65.437,-56.724 ; 63.05,-53.244 63.05,-53.092 63.431,-52.711 ; 63.05,-53.244 62.618,-53.244 62.872,-52.99 63.075,-52.99 63.354,-52.711 63.431,-52.711 ; 63.05,-53.244 63.304,-53.244 63.456,-53.092 ; 63.202,-52.33 63.71,-51.822 64.243,-51.822 ; 63.202,-52.33 64.396,-52.33 64.497,-52.33 ; 63.456,-53.575 63.659,-53.575 ; 63.456,-53.575 63.456,-53.092 ; 63.456,-53.092 63.837,-53.092 ; 63.456,-53.092 64.015,-52.533 64.193,-52.533 64.396,-52.533 ; 63.659,-53.575 63.685,-53.6 ; 63.659,-53.575 63.685,-53.549 ; 63.685,-53.6 63.685,-53.549 ; 63.685,-53.6 63.888,-53.803 ; 63.685,-53.549 63.685,-53.244 63.837,-53.092 ; 63.685,-53.549 63.761,-53.473 ; 63.761,-53.473 63.909,-53.325 63.913,-53.321 63.913,-53.092 ; 63.761,-53.473 63.909,-53.473 64.218,-53.473 ; 63.837,-53.092 63.909,-53.092 63.913,-53.092 ; 63.837,-53.092 63.909,-53.02 64.396,-52.533 ; 63.888,-53.803 63.909,-53.824 64.062,-53.978 64.062,-53.629 ; 63.888,-53.803 63.532,-54.159 63.532,-54.438 63.909,-54.061 63.913,-54.057 64.159,-54.057 64.345,-54.057 64.497,-53.905 ; 63.888,-53.803 63.909,-53.782 64.062,-53.629 ; 63.913,-53.092 64.497,-53.092 ; 63.913,-53.092 64.497,-52.508 ; 64.062,-53.629 64.218,-53.473 ; 64.218,-53.473 64.497,-53.473 ; 64.218,-53.473 64.497,-53.194 ; 64.243,-51.822 64.574,-52.152 ; 64.243,-51.822 64.116,-51.695 64.116,-51.441 64.167,-51.492 65.132,-51.492 65.266,-51.625 65.463,-51.822 64.904,-51.822 ; 64.243,-51.822 64.904,-51.822 ; 64.396,-52.533 64.497,-52.432 ; T1.7@64.497,-54.438 64.497,-54.362 64.497,-53.905 ; T1.7@64.497,-54.438 64.904,-54.438 65.133,-54.668 T1.7@65.437,-54.972 ; T1.7@64.497,-54.438 64.599,-54.337 64.599,-54.26 64.599,-53.803 ; 64.497,-53.905 64.497,-53.473 ; 64.497,-53.905 64.599,-53.803 ; 64.497,-53.473 64.497,-53.194 ; 64.497,-53.473 64.599,-53.473 ; 64.497,-53.194 64.497,-53.092 ; 64.497,-53.194 64.561,-53.13 ; 64.497,-53.092 64.497,-52.508 ; 64.497,-53.092 64.523,-53.092 64.561,-53.13 ; 64.497,-52.508 64.497,-52.432 ; 64.497,-52.508 64.599,-52.406 ; 64.497,-52.432 64.497,-52.33 ; 64.497,-52.432 64.599,-52.33 ; 64.497,-52.33 64.497,-52.228 64.574,-52.152 ; 64.497,-52.33 64.599,-52.33 ; 64.561,-53.13 64.599,-53.168 ; 64.561,-53.13 64.599,-53.092 ; 64.574,-52.152 64.904,-51.822 ; 64.574,-52.152 64.751,-52.33 ; 64.599,-53.803 64.599,-53.473 ; 64.599,-53.803 64.916,-53.486 ; 64.599,-53.473 64.599,-53.168 ; 64.599,-53.473 64.646,-53.426 64.672,-53.426 64.764,-53.333 ; 64.599,-53.168 64.599,-53.092 ; 64.599,-53.168 64.764,-53.333 ; 64.599,-53.092 64.599,-52.406 ; 64.599,-53.092 64.853,-52.838 ; 64.599,-52.406 64.599,-52.33 ; 64.599,-52.33 64.751,-52.33 ; 64.751,-52.33 65.361,-52.33 ; 64.764,-53.333 64.916,-53.486 ; 64.764,-53.333 64.929,-53.168 65.082,-53.321 ; 64.853,-52.838 65.361,-52.33 ; 64.853,-52.838 65.437,-52.838 ; 64.916,-53.486 65.158,-53.727 65.158,-53.397 65.082,-53.321 ; 64.916,-53.486 65.082,-53.321 ; 65.082,-53.321 65.437,-52.965 ; 65.361,-52.33 66.352,-52.33 65.971,-52.711 65.437,-53.244 ; 65.437,-56.724 T1.7@65.437,-56.47 ; T1.7@65.437,-56.47 T1.7@65.437,-55.962 ; T1.7@65.437,-55.962 65.437,-55.642 T1.7@65.437,-54.972 ; T1.7@65.437,-54.972 65.437,-53.956 ; 65.437,-53.956 65.437,-53.244 ; 65.437,-53.244 65.437,-52.965 ; 65.437,-52.965 65.437,-52.838
  Bottom Layer w1.016: 56.192,-51.568 56.192,-50.984 55.887,-50.679 58.368,-50.679 87.571,-50.679 ; T1.7@64.396,-54.464 64.421,-54.438 64.497,-54.362 64.599,-54.26 64.802,-54.057 ; 64.447,-51.187 88.15,-51.187 ; 64.701,-51.822 64.904,-51.822 65.463,-51.822 86.903,-51.822 87.1,-51.625 87.3,-51.425 ; 65.844,-52.33 66.352,-52.33 67.063,-52.33 85.021,-52.33 ; 85.236,-52.115 85.021,-52.33 ; 86.625,-51.425 87.3,-51.425 ; 87.325,-51.4 87.3,-51.425 ; 88.825,-51.175 89.425,-51.175 90.95,-49.65 ; 90.6,-51.9 90.125,-51.425 87.3,-51.425 ; 90.8,-48.7 88.313,-51.187 88.15,-51.187 ; 90.85,-47.4 87.571,-50.679 ; 91.372,-53.675 90.027,-52.33 85.021,-52.33 ; 87.571,-50.679 88.15,-50.679 88.15,-51.187
U4_1: U1.1 ZD1.1
U4_2: D8.1 D9.1 U1.2
U4_3: R31.2 R34.2 U1.3 | length 6.4
  Bottom Layer w0.8: R31.2@103.995,-25.325 103.995,-25.345 105.92,-27.27 U1.3@105.92,-29.476 ; U1.3@106.195,-29.476 107.531,-29.476 R34.2@107.63,-29.575

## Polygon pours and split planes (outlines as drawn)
GND on Bottom Layer "Bottom Layer-No Net" (solid): 94.81,-30.3 95.49,-31.56 95.76,-30.93 96.13,-31.53 96.41,-30.93 96.68,-31.49 96.95,-30.93 97.33,-31.5 97.73,-30.79 97.46,-29.78 96.37,-29.57 95.46,-29.64
U3_3 on Bottom Layer "Bottom Layer-No Net" (solid): 95.17,-39.17 95.89,-38.07 96.23,-38.66 96.54,-38.08 96.89,-38.68 97.28,-38.1 97.77,-38.91 97.4,-39.62 95.61,-39.79
D2_2 on Bottom Layer "Bottom Layer-No Net" (solid): 99.63,-22.07 99.62,-22.08 98.45,-22.08 ccw(c98.45,-22.5) 98.03,-22.5 98.03,-22.8 98.03,-25.73 ccw(c98.54,-25.73) 98.54,-26.24 99.75,-26.24 ccw(c99.75,-25.75) 100.24,-25.75 100.24,-22.68 ccw(c99.63,-22.68) 99.63,-22.07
